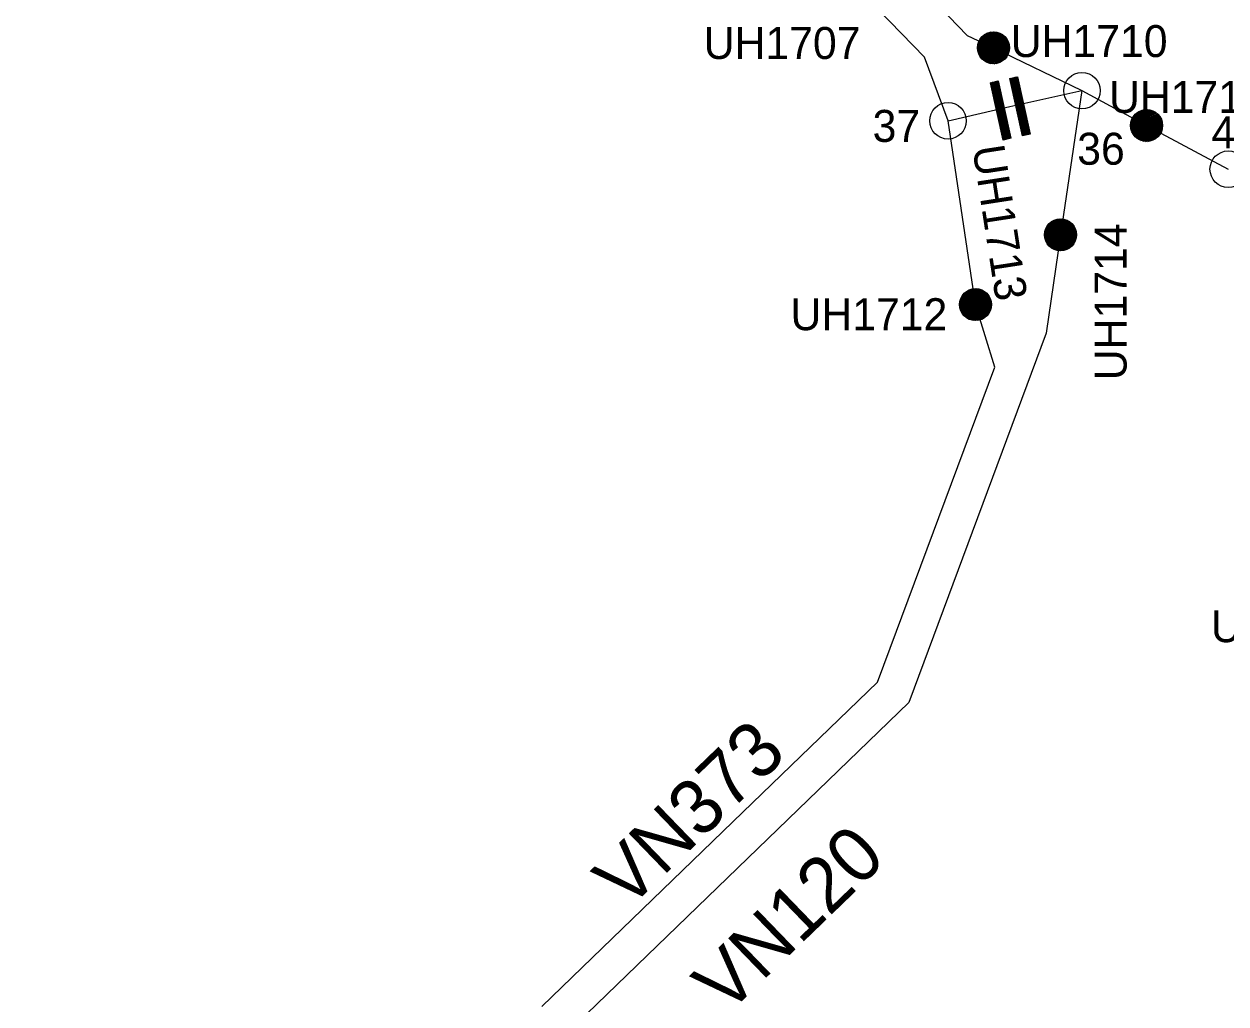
# Model space of a CAD drawing. Extents: x -541380 to -536551, y -1184364 to -1179471.
# Drawn here: x -539865 to -538549, y -1182623 to -1181550 of the extents above; entities that cross this region are included whole.
import ezdxf

# ---------------------------------------------------------------- set-up
doc = ezdxf.new("R2010")
doc.units = 0
for name, color, linetype in [('Default', 7, 'Continuous'), ('Vrstva 1', 7, 'Continuous'), ('Vrstva 2', 7, 'Continuous'), ('Vrstva 5', 7, 'Continuous')]:
    doc.layers.add(name, color=color, linetype=linetype)

# ---------------------------------------------------------------- blocks, each defined once
blk = doc.blocks.new('PS140')
at = {"layer": 'Default'}
for p, q in [((-17.5, 0), (0, 17.5)), ((-17.4, -1.4), (1.4, 17.4)), ((-17.4, 1.5), (-1.5, 17.4)), ((-17.3, -2.6), (2.6, 17.3)), ((-17.2, 3.1), (-3.1, 17.2)), ((-17.1, -3.8), (3.8, 17.1)), ((-16.8, -4.9), (4.9, 16.8)), ((-16.8, 5), (-5, 16.8)), ((-16.4, -6), (6, 16.4)), ((-16, -7), (7, 16)), ((-15.9, 7.2), (-7.2, 15.9)), ((-15.6, -8), (8, 15.6)), ((-15.1, -8.9), (8.9, 15.1)), ((-14.5, -9.8), (9.8, 14.5)), ((-13.9, -10.6), (10.6, 13.9)), ((-13.8, 10.8), (-10.8, 13.8)), ((-13.3, -11.4), (11.4, 13.3)), ((-12.6, -12.1), (12.1, 12.6)), ((-11.9, -12.8), (12.8, 11.9)), ((-11.2, -13.5), (13.5, 11.2)), ((-10.4, -14.1), (14.1, 10.4)), ((-9.5, -14.7), (14.7, 9.5)), ((-8.6, -15.2), (15.2, 8.6)), ((-7.7, -15.7), (15.7, 7.7)), ((-6.7, -16.1), (16.1, 6.7)), ((-5.7, -16.5), (16.5, 5.7)), ((-4.6, -16.9), (16.9, 4.6)), ((-3.5, -17.1), (17.1, 3.5)), ((-2.3, -17.3), (17.3, 2.3)), ((-1, -17.5), (17.5, 1)), ((0.4, -17.5), (17.5, -0.4)), ((1.9, -17.4), (17.4, -1.9)), ((3.6, -17.1), (17.1, -3.6)), ((5.5, -16.6), (16.6, -5.5)), ((8, -15.6), (15.6, -8))]:
    blk.add_line(p, q, dxfattribs=at)
blk.add_circle((0, 0), 17.5, dxfattribs=at)
blk = doc.blocks.new('PS150')
at = {"layer": 'Default'}
for p, q in [((-15.1, 22.4), (-7.4, 30.1)), ((-15.1, 23.8), (-8.8, 30.1)), ((-15.1, 25.2), (-10.2, 30.1)), ((-15.1, 26.6), (-11.6, 30.1)), ((-15.1, 28), (-13, 30.1)), ((-15.1, 29.4), (-14.4, 30.1)), ((-15.1, 20.9), (-6.5, 29.5)), ((-15.1, 19.5), (-6.5, 28.1)), ((-15.1, 18.1), (-6.5, 26.7)), ((6.7, 22.6), (14.1, 30.1)), ((6.7, 24), (12.7, 30.1)), ((6.7, 25.4), (11.3, 30.1)), ((6.7, 26.8), (9.9, 30.1)), ((6.7, 28.3), (8.5, 30.1)), ((6.7, 29.7), (7, 30.1)), ((6.7, 21.2), (15.2, 29.8)), ((6.7, 19.8), (15.2, 28.3)), ((6.7, 18.4), (15.2, 26.9)), ((-15.1, 16.7), (-6.5, 25.3)), ((-15.1, 15.3), (-6.5, 23.9)), ((-15.1, 13.9), (-6.5, 22.4)), ((-15.1, 12.5), (-6.5, 21)), ((-15.1, 11), (-6.5, 19.6)), ((-15.1, 9.6), (-6.5, 18.2)), ((-15.1, 8.2), (-6.5, 16.8)), ((-15.1, 6.8), (-6.5, 15.4)), ((-15.1, 5.4), (-6.5, 14)), ((6.7, 16.9), (15.2, 25.5)), ((6.7, 15.5), (15.2, 24.1)), ((6.7, 14.1), (15.2, 22.7)), ((6.7, 12.7), (15.2, 21.3)), ((6.7, 11.3), (15.2, 19.9)), ((6.7, 9.9), (15.2, 18.4)), ((6.7, 8.5), (15.2, 17)), ((6.7, 7.1), (15.2, 15.6)), ((6.7, 5.6), (15.2, 14.2)), ((-15.1, 4), (-6.5, 12.5)), ((-15.1, 2.6), (-6.5, 11.1)), ((-15.1, 1.2), (-6.5, 9.7)), ((-15.1, -0.3), (-6.5, 8.3)), ((-15.1, -1.7), (-6.5, 6.9)), ((-15.1, -3.1), (-6.5, 5.5)), ((-15.1, -4.5), (-6.5, 4.1)), ((-15.1, -5.9), (-6.5, 2.6)), ((-15.1, -7.3), (-6.5, 1.2)), ((6.7, 4.2), (15.2, 12.8)), ((6.7, 2.8), (15.2, 11.4)), ((6.7, 1.4), (15.2, 10)), ((6.7, 0), (15.2, 8.5)), ((6.7, -1.4), (15.2, 7.1)), ((6.7, -2.8), (15.2, 5.7)), ((6.7, -4.3), (15.2, 4.3)), ((6.7, -5.7), (15.2, 2.9)), ((6.7, -7.1), (15.2, 1.5)), ((6.7, -8.5), (15.2, 0.1)), ((-15.1, -8.7), (-6.5, -0.2)), ((-15.1, -10.2), (-6.5, -1.6)), ((-15.1, -11.6), (-6.5, -3)), ((-15.1, -13), (-6.5, -4.4)), ((-15.1, -14.4), (-6.5, -5.8)), ((-15.1, -15.8), (-6.5, -7.3)), ((-15.1, -17.2), (-6.5, -8.7)), ((-15.1, -18.6), (-6.5, -10.1)), ((-15.1, -20.1), (-6.5, -11.5)), ((-15.1, -21.5), (-6.5, -12.9)), ((6.7, -9.9), (15.2, -1.4)), ((6.7, -11.3), (15.2, -2.8)), ((6.7, -12.7), (15.2, -4.2)), ((6.7, -14.2), (15.2, -5.6)), ((6.7, -15.6), (15.2, -7)), ((6.7, -17), (15.2, -8.4)), ((6.7, -18.4), (15.2, -9.8)), ((6.7, -19.8), (15.2, -11.3)), ((6.7, -21.2), (15.2, -12.7)), ((-15.1, -22.9), (-6.5, -14.3)), ((-15.1, -24.3), (-6.5, -15.7)), ((-15.1, -25.7), (-6.5, -17.2)), ((-15.1, -27.1), (-6.5, -18.6)), ((-15.1, -28.5), (-6.5, -20)), ((-15.1, -30), (-6.5, -21.4)), ((-15.1, -31.4), (-6.5, -22.8)), ((-15.1, -32.8), (-6.5, -24.2)), ((-15, -34.2), (-6.5, -25.6)), ((6.7, -22.6), (15.2, -14.1)), ((6.7, -24.1), (15.2, -15.5)), ((6.7, -25.5), (15.2, -16.9)), ((6.7, -26.9), (15.2, -18.3)), ((6.7, -28.3), (15.2, -19.7)), ((6.7, -29.7), (15.2, -21.2)), ((6.7, -31.1), (15.2, -22.6)), ((6.7, -32.5), (15.2, -24)), ((6.7, -34), (15.2, -25.4)), ((-13.6, -34.2), (-6.5, -27.1)), ((-12.2, -34.2), (-6.5, -28.5)), ((-10.8, -34.2), (-6.5, -29.9)), ((-9.4, -34.2), (-6.5, -31.3)), ((-8, -34.2), (-6.5, -32.7)), ((-6.5, -34.2), (-6.5, -34.1)), ((7.9, -34.2), (15.2, -26.8)), ((9.3, -34.2), (15.2, -28.2)), ((10.7, -34.2), (15.2, -29.6)), ((12.1, -34.2), (15.2, -31)), ((13.5, -34.2), (15.2, -32.5)), ((14.9, -34.2), (15.2, -33.9))]:
    blk.add_line(p, q, dxfattribs=at)
for points in [[(-6.5, 30.1), (-6.5, -34.2), (-15.1, -34.2), (-15.1, 30.1)], [(15.2, 30.1), (15.2, -34.2), (6.7, -34.2), (6.7, 30.1)]]:
    blk.add_lwpolyline(points, close=True, dxfattribs=at)
blk = doc.blocks.new('PS800')
at = {"layer": 'Vrstva 2'}
blk.add_circle((0, 0), 20, dxfattribs=at)

msp = doc.modelspace()

# ---------------------------------------------------------------- linework, layer by layer
at = {"layer": 'Vrstva 1'}
for points in [[(-538853.4, -1181656.3), (-538879.1, -1181586.7), (-538955.1, -1181508)], [(-538872.1, -1181521.4), (-538832.5, -1181562.8), (-538803.6, -1181576.3)], [(-538803.6, -1181576.3), (-538706.7, -1181623.3)], [(-538785.7, -1181640.7), (-538706.7, -1181623.3)], [(-538706.7, -1181623.3), (-538730.2, -1181781.1)], [(-538706.7, -1181623.3), (-538635.9, -1181661.4)], [(-538853.4, -1181656.3), (-538785.7, -1181640.7)], [(-538823.3, -1181857.6), (-538853.4, -1181656.3)], [(-538635.9, -1181661.4), (-538546.5, -1181709.3)], [(-538730.2, -1181781.1), (-538745.8, -1181888.8), (-538896.2, -1182293.4), (-539271.4, -1182655.8), (-539865.4, -1183229.4)], [(-539078.2, -1182413.6), (-538930.5, -1182270.9), (-538802.3, -1181926.1), (-538823.3, -1181857.6)], [(-539298.4, -1182626.3), (-539078.2, -1182413.6)]]:
    msp.add_lwpolyline(points, dxfattribs=at)

# ---------------------------------------------------------------- block references
at = {"layer": 'Vrstva 2'}
for name, p, rotation in [('PS140', (-538803.6, -1181576.3), -16.163635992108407), ('PS150', (-538785.7, -1181640.7), 12.46593864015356), ('PS140', (-538635.9, -1181661.4), -22.518947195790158), ('PS140', (-538730.2, -1181781.1), 92.18886660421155), ('PS140', (-538823.3, -1181857.6), 92.53613051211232)]:
    msp.add_blockref(name, p, dxfattribs=dict(at, rotation=rotation))
at = {"layer": 'Vrstva 5'}
for p, rotation in [((-538706.7, -1181623.3), -86.3980777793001), ((-538853.4, -1181656.3), -16.411086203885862), ((-538546.5, -1181709.3), -17.418355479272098)]:
    msp.add_blockref('PS800', p, dxfattribs=dict(at, rotation=rotation))

# ---------------------------------------------------------------- texts
at = {"layer": 'Vrstva 1'}
for s, p in [('VN373', (-539204.6, -1182521.6)), ('VN120', (-539095.8, -1182636.5))]:
    msp.add_text(s, height=60, rotation=44.007, dxfattribs=at).set_placement(p)
at = {"layer": 'Vrstva 2'}
for s, p in [('UH1707', (-539121, -1181588.6)), ('UH1710', (-538784.7, -1181586.5)), ('UH1716', (-538677.1, -1181647.7)), ('UH1712', (-539025.9, -1181885.6)), ('UH1774', (-538565.5, -1182227.3))]:
    msp.add_text(s, height=35, dxfattribs=at).set_placement(p)
for s, rotation, p in [('UH1713', 278.724, (-538826.8, -1181685.5)), ('UH1714', 90, (-538657.8, -1181940.4))]:
    msp.add_text(s, height=35, rotation=rotation, dxfattribs=at).set_placement(p)
at = {"layer": 'Vrstva 5'}
for s, p in [('37', (-538936, -1181679.4)), ('4', (-538564.9, -1181686.3)), ('36', (-538711.9, -1181704.4))]:
    msp.add_text(s, height=35, dxfattribs=at).set_placement(p)

doc.saveas('drawing.dxf')
